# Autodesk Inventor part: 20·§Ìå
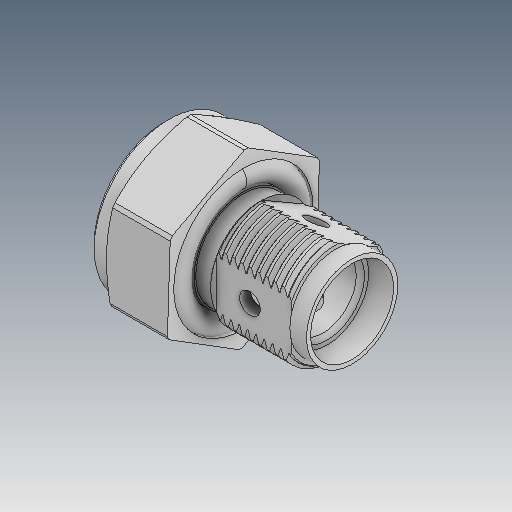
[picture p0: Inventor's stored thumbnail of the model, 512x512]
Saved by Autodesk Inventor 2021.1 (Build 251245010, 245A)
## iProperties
Created: 2019-05
Part Number: 20·§Ìå
Material: Ogólny
Document SubType Name: Modeling
Designer: user
Density: 1 g/cm^3
Appearance: Domyślna
Author: user
Revision Number: ÈÎºÎ
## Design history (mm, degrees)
feature "ÊäÈë1"
feature "ÊäÈë2"
node "Bryła1"
node "Bryła2"
